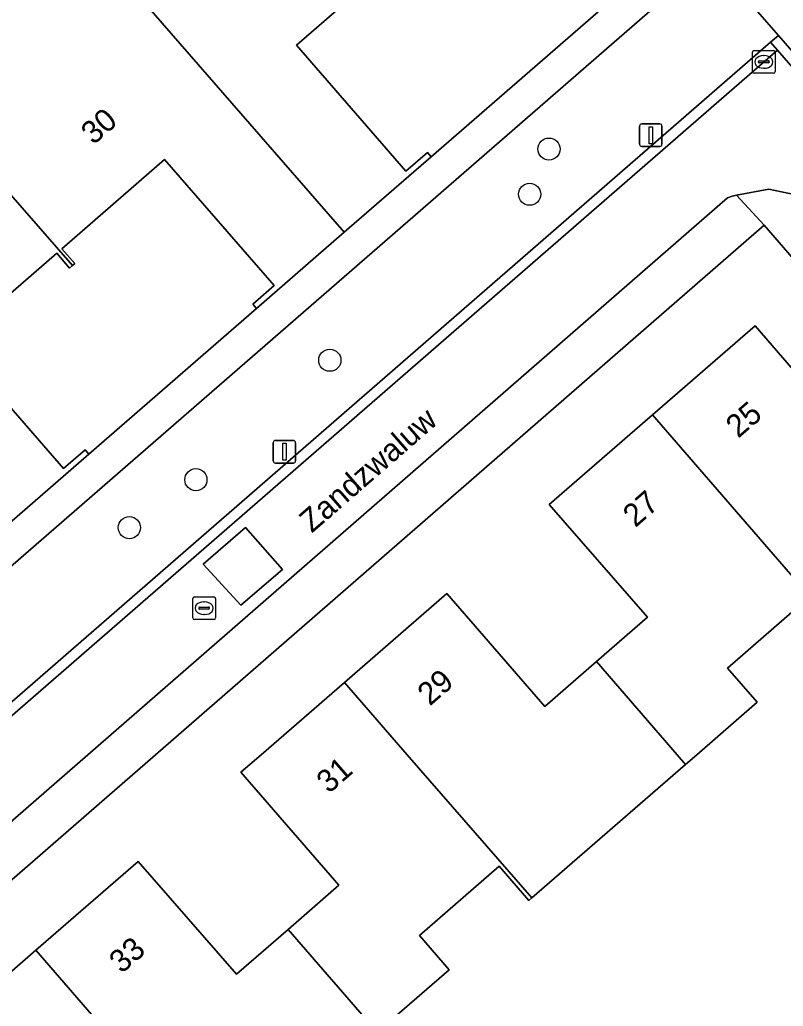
# Model space of a CAD drawing. Extents: x 155887 to 156869, y 383880 to 384678.
# Drawn here: x 156257.89 to 156291.56, y 384238.9 to 384282.42 of the extents above; entities that cross this region are included whole.
import ezdxf

# ---------------------------------------------------------------- set-up
doc = ezdxf.new("R2010")
doc.units = 0
for name, color, linetype in [('IMGEO_Boom', 7, 'Continuous'), ('IMGEO_Erf', 7, 'Continuous'), ('IMGEO_Kolk', 7, 'Continuous'), ('IMGEO_Lichtmast', 7, 'Continuous'), ('IMGEO_Openbare_ruimte_label', 7, 'Continuous'), ('IMGEO_Pand', 7, 'Continuous'), ('IMGEO_Pand_nummerreeks', 7, 'Continuous'), ('IMGEO_Parkeervlak_open', 7, 'Continuous'), ('IMGEO_Rijbaan_lokaal_gesloten', 7, 'Continuous'), ('IMGEO_Rijbaan_lokaal_open', 7, 'Continuous'), ('IMGEO_Rioolput', 7, 'Continuous'), ('IMGEO_Voetpad_open', 7, 'Continuous')]:
    doc.layers.add(name, color=color, linetype=linetype)

msp = doc.modelspace()

# ---------------------------------------------------------------- linework, layer by layer
at = {"layer": 'IMGEO_Boom'}
for centre in [(156281.228, 384276.714), (156280.373, 384274.722), (156271.565, 384267.4), (156265.659, 384262.13), (156262.726, 384260.015)]:
    msp.add_circle(centre, 0.489, dxfattribs=at)
at = {"layer": 'IMGEO_Erf'}
for points in [[(156283.4, 384282.776), (156283.237, 384282.965), (156284.208, 384283.81), (156279.374, 384289.373), (156274.845, 384285.438), (156275.416, 384284.782), (156275.317, 384284.696), (156275.19, 384284.585), (156274.619, 384285.241), (156270.089, 384281.305), (156274.923, 384275.741), (156275.868, 384276.562), (156276.031, 384276.373)], [(156268.332, 384269.684), (156268.169, 384269.873), (156269.111, 384270.691), (156264.277, 384276.255), (156259.748, 384272.32), (156260.319, 384271.664), (156260.214, 384271.572), (156260.093, 384271.467), (156259.522, 384272.123), (156254.992, 384268.187), (156259.826, 384262.623), (156260.771, 384263.444), (156260.934, 384263.255)]]:
    msp.add_lwpolyline(points, close=True, dxfattribs=at)
for points in [[(156254.07, 384237.439), (156258.604, 384241.375), (156263.119, 384245.295), (156267.446, 384240.312), (156269.721, 384242.29), (156271.969, 384244.244), (156267.642, 384249.227), (156268.532, 384250), (156272.206, 384253.19), (156276.719, 384257.109), (156281.046, 384252.126), (156283.323, 384254.106), (156285.57, 384256.06), (156281.243, 384261.043), (156285.798, 384264.997), (156290.313, 384268.918), (156294.634, 384263.937), (156297.051, 384266.029), (156297.28, 384266.215), (156292.266, 384272.02), (156292.04, 384271.827), (156290.715, 384273.351), (156263.88, 384250), (156249.638, 384237.607)], [(156301.28, 384238.058), (156305.386, 384241.63), (156307.289, 384239.443), (156307.705, 384239.805), (156311.312, 384242.941), (156309.999, 384244.45), (156313.281, 384247.304), (156300.978, 384261.493), (156298.308, 384259.173), (156299.355, 384257.963), (156295.078, 384254.265), (156292.732, 384256.978), (156289.096, 384253.821), (156290.406, 384252.311), (156287.745, 384250), (156287.255, 384249.574), (156280.466, 384243.678), (156280.342, 384243.57), (156279.031, 384245.079), (156275.514, 384242.025), (156276.824, 384240.515), (156273.658, 384237.765)]]:
    msp.add_lwpolyline(points, dxfattribs=at)
at = {"layer": 'IMGEO_Kolk'}
for p, q in [((156290.276, 384281.061), (156291.128, 384281.061)), ((156290.201, 384280.135), (156290.201, 384280.987)), ((156290.46, 384280.555), (156290.46, 384280.567)), ((156290.503, 384280.604), (156290.901, 384280.604)), ((156290.689, 384280.841), (156290.714, 384280.841)), ((156290.944, 384280.567), (156290.944, 384280.555)), ((156291.202, 384280.987), (156291.202, 384280.135)), ((156290.898, 384280.518), (156290.5, 384280.518)), ((156290.712, 384280.281), (156290.687, 384280.281)), ((156291.128, 384280.061), (156290.276, 384280.061))]:
    msp.add_line(p, q, dxfattribs=at)
for points in [[(156290.276, 384281.061), (156291.128, 384281.061)], [(156290.201, 384280.135), (156290.201, 384280.987)], [(156291.202, 384280.987), (156291.202, 384280.135)], [(156291.128, 384280.061), (156290.276, 384280.061)]]:
    msp.add_lwpolyline(points, dxfattribs=at)
for centre, radius, start, end in [((156290.278, 384280.985), 0.0765, 91.552, 178.448), ((156290.278, 384280.985), 0.0765, 91.552, 178.448), ((156291.126, 384280.985), 0.0765, 1.552, 88.448), ((156291.126, 384280.985), 0.0765, 1.552, 88.448), ((156290.5, 384280.564), 0.0403, 85.8775, 175.7526), ((156290.497, 384280.554), 0.0366, 178.938, 274.7102), ((156290.901, 384280.561), 0.043, 264.8664, 352.4533), ((156290.905, 384280.566), 0.0386, 1.7309, 96.639), ((156290.278, 384280.137), 0.0765, 181.552, 268.448), ((156290.278, 384280.137), 0.0765, 181.552, 268.448), ((156291.126, 384280.137), 0.0765, 271.552, 358.448), ((156291.126, 384280.137), 0.0765, 271.552, 358.448)]:
    msp.add_arc(centre, radius, start, end, dxfattribs=at)
for centre, major_axis, ratio, start_param, end_param in [((156290.688, 384280.561), (-0.387, 0.002), 0.722429, 4.712389, 7.853982), ((156290.713, 384280.561), (-0.39, 0.002), 0.717154, 1.570796, 4.712389)]:
    msp.add_ellipse(centre, major_axis=major_axis, ratio=ratio, start_param=start_param, end_param=end_param, dxfattribs=at)
at = {"layer": 'IMGEO_Lichtmast'}
for p, q in [((156285.222, 384276.928), (156285.222, 384277.728)), ((156285.222, 384277.728), (156285.222, 384276.928)), ((156285.322, 384277.828), (156286.112, 384277.828)), ((156286.112, 384277.828), (156285.322, 384277.828)), ((156286.212, 384277.728), (156286.212, 384276.928)), ((156286.212, 384276.928), (156286.212, 384277.728)), ((156286.112, 384276.828), (156285.322, 384276.828)), ((156285.322, 384276.828), (156286.112, 384276.828)), ((156269.067, 384262.961), (156269.067, 384263.761)), ((156269.067, 384263.761), (156269.067, 384262.961)), ((156269.167, 384263.861), (156269.957, 384263.861)), ((156269.957, 384263.861), (156269.167, 384263.861)), ((156270.057, 384263.761), (156270.057, 384262.961)), ((156270.057, 384262.961), (156270.057, 384263.761)), ((156269.957, 384262.861), (156269.167, 384262.861)), ((156269.167, 384262.861), (156269.957, 384262.861))]:
    msp.add_line(p, q, dxfattribs=at)
for points in [[(156285.642, 384277.703), (156285.792, 384277.703), (156285.792, 384276.953), (156285.642, 384276.953), (156285.642, 384277.703)], [(156269.487, 384263.736), (156269.637, 384263.736), (156269.637, 384262.986), (156269.487, 384262.986), (156269.487, 384263.736)]]:
    msp.add_lwpolyline(points, dxfattribs=at)
for centre, start, end in [((156285.322, 384277.728), 90, 180), ((156285.322, 384277.728), 90, 180), ((156286.112, 384277.728), 0, 90), ((156286.112, 384277.728), 360, 90), ((156285.322, 384276.928), 180, 270), ((156285.322, 384276.928), 180, 270), ((156286.112, 384276.928), 270, 0), ((156286.112, 384276.928), 270, 0), ((156269.167, 384263.761), 90, 180), ((156269.167, 384263.761), 90, 180), ((156269.957, 384263.761), 0, 90), ((156269.957, 384263.761), 360, 90), ((156269.167, 384262.961), 180, 270), ((156269.167, 384262.961), 180, 270), ((156269.957, 384262.961), 270, 0), ((156269.957, 384262.961), 270, 0)]:
    msp.add_arc(centre, 0.1, start, end, dxfattribs=at)
at = {"layer": 'IMGEO_Pand'}
for points in [[(156268.062, 384293.044), (156264.431, 384289.889), (156259.767, 384295.255), (156257.18, 384293.007), (156255.842, 384291.844), (156272.197, 384273.042), (156276.031, 384276.373), (156275.868, 384276.562), (156274.923, 384275.741), (156270.089, 384281.305), (156274.619, 384285.241), (156275.19, 384284.585), (156275.317, 384284.696)], [(156255.842, 384291.844), (156254.725, 384290.873), (156251.887, 384288.407), (156256.551, 384283.041), (156252.943, 384279.906), (156260.214, 384271.572), (156260.319, 384271.664), (156259.748, 384272.32), (156264.277, 384276.255), (156269.111, 384270.691), (156268.169, 384269.873), (156268.332, 384269.684), (156272.197, 384273.042)], [(156260.214, 384271.572), (156252.943, 384279.906), (156249.312, 384276.751), (156244.648, 384282.117), (156240.753, 384278.732), (156257.1, 384259.924), (156260.934, 384263.255), (156260.771, 384263.444), (156259.826, 384262.623), (156254.992, 384268.187), (156259.522, 384272.123), (156260.093, 384271.467)], [(156297.051, 384266.029), (156294.634, 384263.937), (156290.313, 384268.918), (156285.798, 384264.997), (156292.732, 384256.978), (156295.078, 384254.265), (156299.355, 384257.963), (156298.308, 384259.173), (156300.978, 384261.493)], [(156287.255, 384249.574), (156287.745, 384250), (156290.406, 384252.311), (156289.096, 384253.821), (156292.732, 384256.978), (156285.798, 384264.997), (156281.243, 384261.043), (156285.57, 384256.06), (156283.323, 384254.106), (156286.885, 384250)], [(156287.255, 384249.574), (156286.885, 384250), (156283.323, 384254.106), (156281.046, 384252.126), (156276.719, 384257.109), (156272.206, 384253.19), (156274.976, 384250), (156280.466, 384243.678)], [(156272.206, 384253.19), (156268.532, 384250), (156267.642, 384249.227), (156271.969, 384244.244), (156269.721, 384242.29), (156273.658, 384237.765), (156276.824, 384240.515), (156275.514, 384242.025), (156279.031, 384245.079), (156280.342, 384243.57), (156280.466, 384243.678), (156274.976, 384250)], [(156258.604, 384241.375), (156265.545, 384233.366), (156269.153, 384236.5), (156270.464, 384234.991), (156273.658, 384237.765), (156269.721, 384242.29), (156267.446, 384240.312), (156263.119, 384245.295)], [(156258.604, 384241.375), (156254.07, 384237.439), (156258.397, 384232.456), (156255.981, 384230.358), (156259.915, 384225.828), (156263.236, 384228.712), (156261.925, 384230.222), (156265.545, 384233.366)]]:
    msp.add_lwpolyline(points, close=True, dxfattribs=at)
at = {"layer": 'IMGEO_Parkeervlak_open'}
msp.add_lwpolyline([(156291.002, 384281.43), (156291.342, 384281.726), (156288.362, 384285.147), (156247.93, 384250), (156242.787, 384245.529), (156245.758, 384242.109), (156254.838, 384250)], close=True, dxfattribs=at)
at = {"layer": 'IMGEO_Rijbaan_lokaal_gesloten'}
msp.add_lwpolyline([(156246.061, 384237.089), (156260.888, 384250), (156289.1, 384274.566), (156289.299, 384274.644), (156289.497, 384274.681), (156290.917, 384274.946), (156292.316, 384274.645), (156292.55, 384274.55), (156293.415, 384274.035), (156293.563, 384273.891), (156295.786, 384275.916), (156291.303, 384281.083), (156255.539, 384250), (156246.06, 384241.762), (156243.102, 384239.116), (156204.848, 384205.921), (156197.157, 384199.948), (156195.594, 384198.757), (156195.167, 384198.429)], dxfattribs=at)
msp.add_lwpolyline([(156265.982, 384258.403), (156267.853, 384260.018), (156269.485, 384258.172), (156267.635, 384256.588)], close=True, dxfattribs=at)
at = {"layer": 'IMGEO_Rijbaan_lokaal_open'}
for points in [[(156291.303, 384281.083), (156291.002, 384281.43), (156254.838, 384250), (156245.758, 384242.109), (156242.8, 384239.463), (156204.556, 384206.277), (156196.854, 384200.295), (156195.238, 384199.063), (156195.103, 384198.952)], [(156195.167, 384198.429), (156195.594, 384198.757), (156197.157, 384199.948), (156204.848, 384205.921), (156243.102, 384239.116), (156246.06, 384241.762), (156255.539, 384250), (156291.303, 384281.083)]]:
    msp.add_lwpolyline(points, dxfattribs=at)
for points in [[(156291.342, 384281.726), (156291.002, 384281.43), (156291.303, 384281.083), (156295.786, 384275.916), (156296.121, 384276.22)], [(156267.635, 384256.588), (156269.485, 384258.172), (156267.853, 384260.018), (156265.982, 384258.403)]]:
    msp.add_lwpolyline(points, close=True, dxfattribs=at)
at = {"layer": 'IMGEO_Rioolput'}
for p, q in [((156265.523, 384256.036), (156265.523, 384256.888)), ((156265.598, 384256.962), (156266.45, 384256.962)), ((156266.011, 384256.742), (156266.036, 384256.742)), ((156266.524, 384256.888), (156266.524, 384256.036)), ((156265.782, 384256.456), (156265.782, 384256.468)), ((156266.22, 384256.419), (156265.822, 384256.419)), ((156265.825, 384256.505), (156266.223, 384256.505)), ((156266.266, 384256.468), (156266.266, 384256.456)), ((156266.45, 384255.962), (156265.598, 384255.962)), ((156266.034, 384256.182), (156266.009, 384256.182))]:
    msp.add_line(p, q, dxfattribs=at)
for points in [[(156265.523, 384256.036), (156265.523, 384256.888)], [(156265.598, 384256.962), (156266.45, 384256.962)], [(156266.524, 384256.888), (156266.524, 384256.036)], [(156266.45, 384255.962), (156265.598, 384255.962)]]:
    msp.add_lwpolyline(points, dxfattribs=at)
for centre, radius, start, end in [((156265.6, 384256.886), 0.0765, 91.552, 178.448), ((156265.6, 384256.886), 0.0765, 91.552, 178.448), ((156266.448, 384256.886), 0.0765, 1.552, 88.448), ((156266.448, 384256.886), 0.0765, 1.552, 88.448), ((156265.822, 384256.465), 0.0403, 85.8775, 175.7526), ((156265.819, 384256.455), 0.0366, 178.938, 274.7102), ((156266.223, 384256.462), 0.043, 264.8664, 352.4533), ((156266.227, 384256.467), 0.0386, 1.7309, 96.639), ((156265.6, 384256.038), 0.0765, 181.552, 268.448), ((156265.6, 384256.038), 0.0765, 181.552, 268.448), ((156266.448, 384256.038), 0.0765, 271.552, 358.448), ((156266.448, 384256.038), 0.0765, 271.552, 358.448)]:
    msp.add_arc(centre, radius, start, end, dxfattribs=at)
for centre, major_axis, ratio, start_param, end_param in [((156266.01, 384256.462), (-0.387, 0.002), 0.722429, 4.712389, 7.853982), ((156266.035, 384256.462), (-0.39, 0.002), 0.717154, 1.570796, 4.712389)]:
    msp.add_ellipse(centre, major_axis=major_axis, ratio=ratio, start_param=start_param, end_param=end_param, dxfattribs=at)
at = {"layer": 'IMGEO_Voetpad_open'}
for points in [[(156295.435, 384280.018), (156292.888, 384283.087), (156247.015, 384335.884), (156245.448, 384334.593), (156249.355, 384330.069), (156256.341, 384321.946), (156258.613, 384319.304), (156271.067, 384305.073), (156287.4, 384286.252), (156288.362, 384285.147), (156291.342, 384281.726), (156296.121, 384276.22), (156318.88, 384250), (156326.424, 384241.306)], [(156323.695, 384239.126), (156314.264, 384250), (156298.985, 384267.615), (156293.563, 384273.891), (156293.415, 384274.035), (156292.55, 384274.55), (156292.316, 384274.645), (156290.917, 384274.946), (156289.497, 384274.681), (156290.715, 384273.351), (156292.04, 384271.827), (156292.266, 384272.02), (156297.28, 384266.215), (156297.051, 384266.029), (156300.978, 384261.493), (156313.281, 384247.304), (156317.207, 384242.78), (156317.444, 384242.973), (156322.738, 384236.866)], [(156263.88, 384250), (156290.715, 384273.351), (156289.497, 384274.681), (156289.299, 384274.644), (156289.1, 384274.566), (156260.888, 384250), (156246.061, 384237.089), (156208.721, 384204.654)], [(156200.017, 384196.613), (156199.543, 384196.155), (156199.071, 384195.696), (156198.6, 384195.236), (156198.918, 384194.869), (156199.564, 384194.123), (156201.062, 384195.394), (156242.149, 384231.047), (156246.679, 384234.978), (156249.638, 384237.607), (156263.88, 384250)]]:
    msp.add_lwpolyline(points, dxfattribs=at)
msp.add_lwpolyline([(156288.362, 384285.147), (156287.4, 384286.252), (156283.4, 384282.776), (156276.031, 384276.373), (156272.197, 384273.042), (156268.332, 384269.684), (156260.934, 384263.255), (156257.1, 384259.924), (156253.235, 384256.566), (156245.845, 384250.143), (156245.68, 384250), (156241.836, 384246.66), (156242.787, 384245.529), (156247.93, 384250)], close=True, dxfattribs=at)

# ---------------------------------------------------------------- texts
at = {"layer": 'IMGEO_Openbare_ruimte_label'}
msp.add_text('Zandzwaluw', height=1, rotation=41.0241, dxfattribs=at).set_placement((156270.77, 384259.753))
at = {"layer": 'IMGEO_Pand_nummerreeks'}
for s, rotation, p in [('30', 40.9894, (156261.143, 384276.871)), ('25', 40.9665, (156289.573, 384263.931)), ('27', 40.9661, (156285.037, 384259.994)), ('29', 40.9694, (156275.976, 384252.121)), ('31', 40.9694, (156271.523, 384248.254)), ('33', 40.9633, (156262.383, 384240.313))]:
    msp.add_text(s, height=1, rotation=rotation, dxfattribs=at).set_placement(p)

doc.saveas('drawing.dxf')
